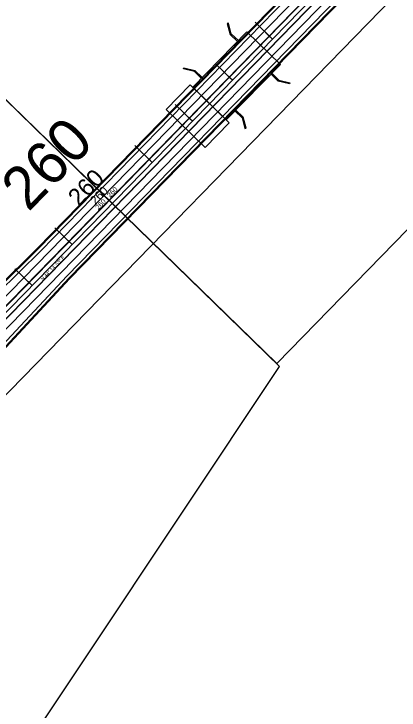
# Model space of a CAD drawing. Extents: x 2358865 to 2362945, y 393485 to 404880.
# Drawn here: x 2359906 to 2360577, y 397563 to 398777 of the extents above; entities that cross this region are included whole.
import ezdxf

# ---------------------------------------------------------------- set-up
doc = ezdxf.new("R2010")
doc.units = 0
for name, color, linetype in [('CL', 7, 'Continuous'), ('Counterweight Housing', 7, 'Continuous'), ('Level 19', 7, 'Continuous'), ('Level 21', 7, 'Continuous'), ('Level 25', 7, 'Continuous'), ('Level 27', 7, 'Continuous'), ('Level 30', 7, 'Continuous'), ('Level 35', 7, 'Continuous'), ('Level 37', 7, 'Continuous'), ('Level 39', 7, 'Continuous'), ('Level 41', 7, 'Continuous'), ('Level 48', 7, 'Continuous'), ('Level 58', 7, 'Continuous'), ('Level 63', 7, 'Continuous'), ('Moveable Span', 7, 'Continuous'), ('STAEQU', 7, 'Continuous')]:
    doc.layers.add(name, color=color, linetype=linetype)

msp = doc.modelspace()

# ---------------------------------------------------------------- linework, layer by layer
at = {"layer": 'CL'}
msp.add_line((2359688.9, 398047.8), (2361589.9, 399999.4), dxfattribs=at)
at = {"layer": 'Counterweight Housing'}
for p, q in [((2360171.4, 398610.6), (2360213.2, 398653.6)), ((2360281.3, 398587.3), (2360213.2, 398653.6)), ((2360171.4, 398610.6), (2360239.4, 398544.4)), ((2360239.4, 398544.4), (2360281.3, 398587.3))]:
    msp.add_line(p, q, dxfattribs=at)
at = {"layer": 'Level 19'}
for p, q in [((2359821.6, 398212.7), (2361205.3, 399633.2)), ((2359850.3, 398184.8), (2361234, 399605.3))]:
    msp.add_line(p, q, dxfattribs=at)
at = {"layer": 'Level 25'}
for p, q in [((2360356.4, 398733.1), (2360352.8, 398736.6)), ((2360286.6, 398661.4), (2360283, 398664.9)), ((2360216.9, 398589.8), (2360213.3, 398593.3)), ((2360147.1, 398518.2), (2360143.5, 398521.7)), ((2360077.3, 398446.5), (2360071.6, 398452.1)), ((2360007.5, 398374.9), (2360003.9, 398378.4)), ((2359937.7, 398303.3), (2359934.2, 398306.8))]:
    msp.add_line(p, q, dxfattribs=at)
at = {"layer": 'Level 27'}
msp.add_line((2359817.5, 398036.5), (2361439.8, 399702), dxfattribs=at)
at = {"layer": 'Level 30'}
for p, q in [((2360356.4, 398733.1), (2360350.3, 398739)), ((2360286.6, 398661.4), (2360280.5, 398667.4)), ((2360216.9, 398589.8), (2360210.8, 398595.7)), ((2360147.1, 398518.2), (2360141, 398524.1)), ((2360077.3, 398446.5), (2360065.8, 398457.7)), ((2360007.5, 398374.9), (2360001.4, 398380.8)), ((2359937.7, 398303.3), (2359931.7, 398309.2))]:
    msp.add_line(p, q, dxfattribs=at)
at = {"layer": 'Level 35'}
for p, q in [((2359821.6, 398212.7), (2361205.3, 399633.2)), ((2359850.3, 398184.8), (2361234, 399605.3))]:
    msp.add_line(p, q, dxfattribs=at)
at = {"layer": 'Level 37'}
for p, q in [((2359830.2, 398204.4), (2361213.9, 399624.9)), ((2359830.6, 398204), (2361214.3, 399624.5)), ((2359841.3, 398193.6), (2361225, 399614)), ((2359841.7, 398193.2), (2361225.4, 399613.7))]:
    msp.add_line(p, q, dxfattribs=at)
at = {"layer": 'Level 39'}
for p, q in [((2360356.4, 398733.1), (2360344.2, 398744.9)), ((2360286.6, 398661.4), (2360274.5, 398673.3)), ((2360216.9, 398589.8), (2360204.7, 398601.7)), ((2360147.1, 398518.2), (2360134.9, 398530)), ((2360077.3, 398446.5), (2360054.4, 398468.9)), ((2360007.5, 398374.9), (2359995.3, 398386.8)), ((2359937.7, 398303.3), (2359925.6, 398315.1))]:
    msp.add_line(p, q, dxfattribs=at)
at = {"layer": 'Level 41'}
for p, q in [((2360356.4, 398733.1), (2360326.3, 398762.4)), ((2360286.6, 398661.4), (2360256.5, 398690.7)), ((2360216.9, 398589.8), (2360186.8, 398619.1)), ((2360147.1, 398518.2), (2360117, 398547.5)), ((2360077.3, 398446.5), (2360020, 398502.4)), ((2360007.5, 398374.9), (2359977.4, 398404.2)), ((2359937.7, 398303.3), (2359907.7, 398332.6))]:
    msp.add_line(p, q, dxfattribs=at)
at = {"layer": 'Level 48'}
for p, q in [((2361214.3, 399624.5), (2359830.6, 398204)), ((2359841.3, 398193.6), (2361225, 399614))]:
    msp.add_line(p, q, dxfattribs=at)
at = {"layer": 'Level 58'}
for p, q in [((2359947.9, 398369), (2361129.8, 399582.4)), ((2360003.2, 398315.1), (2361185.1, 399528.5)), ((2359769.5, 398193.8), (2359947.9, 398369)), ((2359832.7, 398132.2), (2360003.2, 398315.1))]:
    msp.add_line(p, q, dxfattribs=at)
at = {"layer": 'Level 63'}
for points in [[(2360837.4, 399800.1), (2359790.8, 398725.6), (2360363.8, 398167.4), (2360363.8, 398167.4), (2361410.5, 399241.9), (2361410.5, 399241.9)], [(2360368.8, 398162.6), (2359965.3, 398555.6), (2359965.3, 398555.6), (2359790.8, 398725.6), (2358929.1, 397443.5), (2359114.5, 397249), (2359262, 397221.8), (2359690, 397143), (2359690, 397143)]]:
    msp.add_lwpolyline(points, close=True, dxfattribs=at)
at = {"layer": 'Moveable Span'}
for p, q in [((2360279.6, 398761.1), (2360277.6, 398760.6)), ((2360277.6, 398760.6), (2360282.8, 398741.4)), ((2360284.6, 398742.4), (2360279.6, 398761.1)), ((2360217.9, 398649.1), (2360312.1, 398745.8)), ((2360217.9, 398649.1), (2360312.1, 398745.8)), ((2360312.1, 398745.8), (2360370.3, 398689.1)), ((2360282.8, 398741.4), (2360295.7, 398729)), ((2360297.1, 398730.4), (2360284.6, 398742.4)), ((2360295.7, 398729), (2360297.1, 398730.4)), ((2360201.7, 398681.2), (2360202.2, 398683.2)), ((2360202.2, 398683.2), (2360221.5, 398678.5)), ((2360370.3, 398689.1), (2360276.1, 398592.4)), ((2360220.6, 398676.6), (2360201.7, 398681.2)), ((2360232.9, 398664.5), (2360220.6, 398676.6)), ((2360221.5, 398678.5), (2360234.3, 398665.9)), ((2360353.9, 398672.3), (2360355.3, 398673.7)), ((2360366.6, 398659.7), (2360353.9, 398672.3)), ((2360355.3, 398673.7), (2360367.6, 398661.6)), ((2360234.3, 398665.9), (2360232.9, 398664.5)), ((2360386, 398655), (2360366.6, 398659.7)), ((2360367.6, 398661.6), (2360386.5, 398657)), ((2360276.1, 398592.4), (2360217.9, 398649.1)), ((2360386.5, 398657), (2360386, 398655)), ((2360292.5, 398609.2), (2360291.1, 398607.8)), ((2360291.1, 398607.8), (2360303.5, 398595.8)), ((2360305.4, 398596.8), (2360292.5, 398609.2)), ((2360303.5, 398595.8), (2360308.6, 398577.1)), ((2360310.6, 398577.6), (2360305.4, 398596.8)), ((2360308.6, 398577.1), (2360310.6, 398577.6))]:
    msp.add_line(p, q, dxfattribs=at)
at = {"layer": 'STAEQU'}
for p, q in [((2359949, 398367.9), (2361193.1, 399645.1)), ((2361197.1, 399641.3), (2359953, 398364)), ((2359998.1, 398320.1), (2361242.2, 399597.3)), ((2361246.1, 399593.5), (2360002, 398316.2)), ((2359770.6, 398192.6), (2359949, 398367.9)), ((2359953, 398364), (2359774.6, 398188.8)), ((2359827.6, 398137.2), (2359998.1, 398320.1)), ((2360002, 398316.2), (2359831.5, 398133.3))]:
    msp.add_line(p, q, dxfattribs=at)

# ---------------------------------------------------------------- texts
at = {"layer": 'Level 21'}
msp.add_text('N 44%%d 14\' 53" E', height=6, rotation=45.7519, dxfattribs=at).set_placement((2359956.3, 398311.6))
at = {"layer": 'Level 25'}
for p in [(2360073.6, 398456), (2360053.1, 398434.9)]:
    msp.add_text('260', height=8.75, rotation=45.7519, dxfattribs=at).set_placement(p)
at = {"layer": 'Level 30'}
msp.add_text('260', height=15, rotation=45.7519, dxfattribs=at).set_placement((2360048.1, 398443.4))
at = {"layer": 'Level 39'}
msp.add_text('260', height=30, rotation=45.7519, dxfattribs=at).set_placement((2360019, 398440.3))
at = {"layer": 'Level 41'}
msp.add_text('260', height=75, rotation=45.7519, dxfattribs=at).set_placement((2359931.3, 398430.7))

doc.saveas('drawing.dxf')
